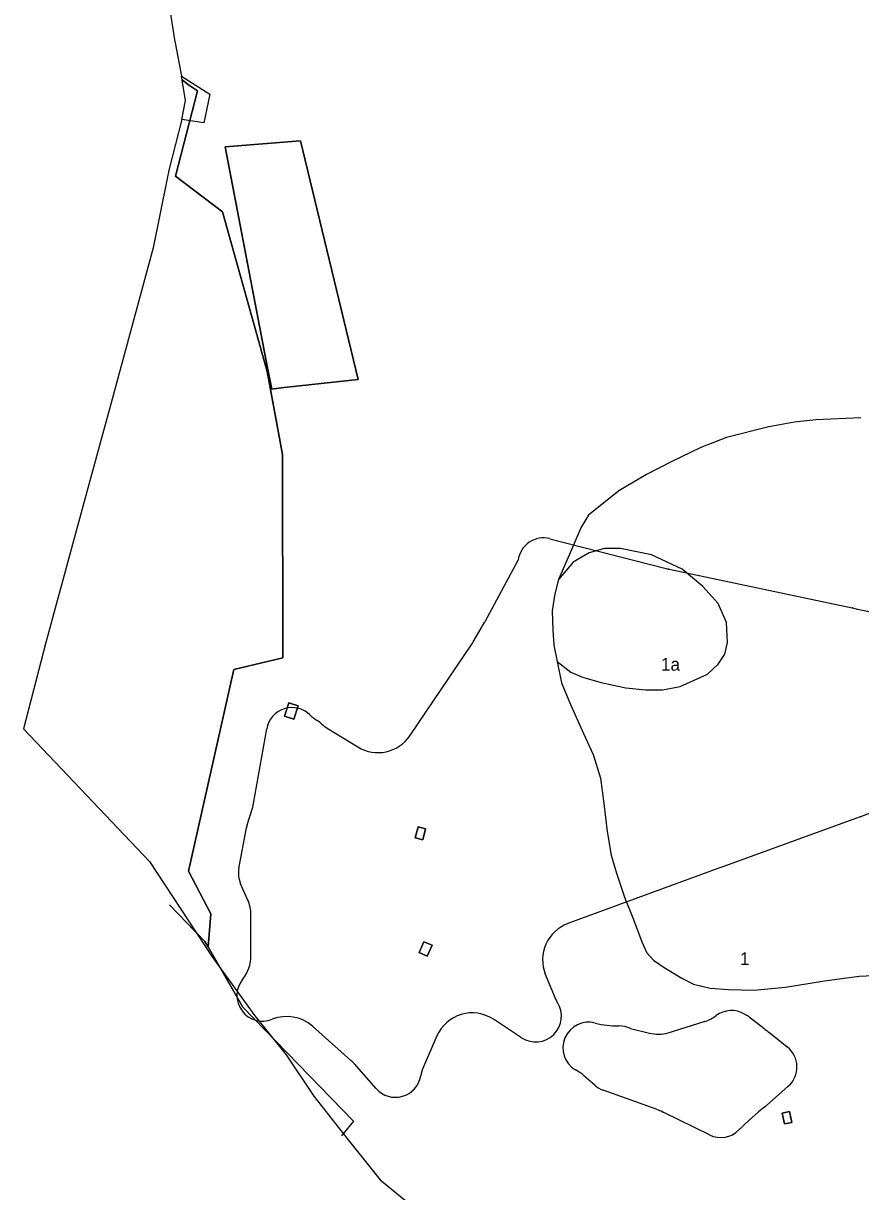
# Model space of a CAD drawing. Extents: x -445049 to -436194, y -1142460 to -1129816.
# Drawn here: x -445049 to -444397, y -1134043 to -1133134 of the extents above; entities that cross this region are included whole.
import ezdxf

# ---------------------------------------------------------------- set-up
doc = ezdxf.new("R2010")
doc.units = 0
for name, color, linetype in [('Vrstva 11', 7, 'Continuous'), ('Vrstva 23', 7, 'Continuous'), ('Vrstva 51', 7, 'Continuous'), ('Vrstva 7', 7, 'Continuous'), ('Vrstva 8', 7, 'Continuous'), ('Vrstva 9', 7, 'Continuous')]:
    doc.layers.add(name, color=color, linetype=linetype)

msp = doc.modelspace()

# ---------------------------------------------------------------- linework, layer by layer
at = {"layer": 'Vrstva 11'}
msp.add_lwpolyline([(-444919.06, -1133836.95), (-444908.06, -1133848.32), (-444905.39, -1133852.69), (-444878.28, -1133899.45), (-444792.06, -1133988.36), (-444801.63, -1133999.84)], dxfattribs=at)
at = {"layer": 'Vrstva 23'}
for p, q in [((-444639.15, -1133534.8), (-444548.63, -1133558.13)), ((-444689.66, -1133599.19), (-444663.98, -1133551.58)), ((-444546.35, -1133558.59), (-444403.74, -1133588.67)), ((-444698.97, -1133615.18), (-444690.15, -1133600.06)), ((-444748.27, -1133688.2), (-444700.03, -1133616.87)), ((-444870.02, -1133740.87), (-444859.79, -1133682.84)), ((-444812.61, -1133682.29), (-444788.88, -1133696.93)), ((-444282.12, -1133707.42), (-444397.22, -1133751.29)), ((-444875.02, -1133757.5), (-444870.97, -1133744.75)), ((-444397.52, -1133751.4), (-444505.41, -1133790.51)), ((-444881.47, -1133791.72), (-444875.63, -1133759.94)), ((-444505.53, -1133790.55), (-444625.29, -1133834.55)), ((-444874.66, -1133815.63), (-444880.07, -1133803.47)), ((-444872.06, -1133859.32), (-444872.06, -1133827.84)), ((-444642.81, -1133873.83), (-444636.02, -1133890.84)), ((-444487.62, -1133904.91), (-444485.19, -1133906.33)), ((-444794.16, -1133940.98), (-444824.22, -1133914.35)), ((-444661.26, -1133923.37), (-444683.23, -1133908.95)), ((-444576.37, -1133916.23), (-444561.62, -1133919.78)), ((-444547.11, -1133919.66), (-444519.18, -1133910.85)), ((-444482.87, -1133907.91), (-444472.63, -1133916.01)), ((-444727.17, -1133921.97), (-444737.71, -1133946.01)), ((-444468.03, -1133919.65), (-444454.39, -1133930.44)), ((-444774.57, -1133962.94), (-444791.51, -1133943.64)), ((-444615.08, -1133950.97), (-444619.34, -1133948.43)), ((-444604.09, -1133960.51), (-444613.05, -1133952.69)), ((-444453.54, -1133961.1), (-444470.43, -1133976.06)), ((-444555.69, -1133979.27), (-444597.67, -1133964.28)), ((-444514.99, -1133999.04), (-444550.55, -1133981.65))]:
    msp.add_line(p, q, dxfattribs=at)
for centre, radius, start, end in [((-444644.14, -1133554.16), 20, 75.54859, 172.58816), ((-444541.75, -1133528.93), 30, 256.73332, 259.94584), ((-444550.48, -1133578.16), 20, 78.0886, 79.94584), ((-444407.87, -1133608.24), 20, 77.17539, 78.0886), ((-443775.03, -1130828.32), 2831.04, 257.17539, 258.46568), ((-444716.06, -1133584.95), 30, 329.73804, 331.65322), ((-444724.88, -1133600.06), 30, 325.93078, 329.73804), ((-444840.09, -1133686.32), 20, 45.52263, 170.00002), ((-444805.06, -1133650.64), 30, 225.52263, 239.14725), ((-444830.7, -1133693.57), 20, 47.41061, 59.14725), ((-444796.86, -1133656.75), 30, 227.41061, 238.32889), ((-444773.12, -1133671.4), 30, 238.32889, 325.93078), ((-444899.56, -1133735.66), 30, 342.37451, 350.00002), ((-444404.34, -1133732.6), 20, 289.92483, 290.86445), ((-444855.96, -1133763.55), 20, 162.37451, 169.58083), ((-444861.8, -1133795.33), 20, 169.58083, 204.00983), ((-444495.18, -1133818.71), 30, 109.92483, 110.17375), ((-444902.06, -1133827.84), 30, 0, 24.00983), ((-444614.94, -1133862.71), 30, 110.17375, 201.74921), ((-444902.06, -1133859.32), 30, 321.43543, 360), ((-444862.97, -1133890.49), 20, 141.43543, 292.14799), ((-444650.28, -1133906.65), 20, 236.71461, 32.59125), ((-444608.16, -1133879.72), 30, 201.74921, 212.59125), ((-444844.12, -1133936.8), 30, 48.46179, 112.14799), ((-444699.7, -1133934.02), 30, 56.71461, 156.31887), ((-444527.28, -1133882.45), 29.52, 286.56502, 306.66618), ((-444497.71, -1133922.17), 20, 59.70458, 126.66618), ((-444495.28, -1133923.59), 20, 51.65172, 59.70458), ((-444609.07, -1133931.26), 20, 74.96204, 239.11851), ((-444586.93, -1133848.85), 65.33, 254.96204, 271.14322), ((-444585.23, -1133934.17), 20, 63.71928, 91.14322), ((-444513.16, -1133929.92), 20, 106.56502, 107.51827), ((-444485.04, -1133931.69), 20, 51.6254, 51.65172), ((-440524.15, -1128929.74), 6360.3, 231.625402, 231.678042), ((-444554.61, -1133890.61), 30, 256.47765, 284.46011), ((-444480.44, -1133935.33), 20, 51.65172, 51.67804), ((-444466.79, -1133946.13), 20, 311.52344, 51.65172), ((-444814.05, -1133963.44), 30, 41.28493, 48.46179), ((-444710.24, -1133958.06), 30, 156.31887, 170.4207), ((-444621.79, -1133960.61), 11.74, 46.39566, 55.18252), ((-444599.89, -1133937.62), 20, 226.39566, 228.87629), ((-444759.54, -1133949.74), 20, 221.28493, 350.4207), ((-444590.94, -1133945.44), 20, 228.87629, 250.34971), ((-444565.86, -1134007.49), 30, 61.17617, 70.18128), ((-444341.71, -1134143.62), 211.25, 127.87599, 135.3404), ((-444483.69, -1133961.09), 20, 307.87599, 311.52344), ((-444541.76, -1133963.68), 20, 241.17617, 243.9304), ((-444506.2, -1133981.08), 20, 243.9304, 315.3404)]:
    msp.add_arc(centre, radius, start, end, dxfattribs=at)
at = {"layer": 'Vrstva 51'}
for points in [[(-444397.1, -1133440.8), (-444432.19, -1133442.27), (-444448.8, -1133444.11), (-444468.62, -1133447.77), (-444501.66, -1133456.09), (-444521.79, -1133463.83), (-444544.75, -1133474.97), (-444564.01, -1133484.84), (-444585.55, -1133497.62), (-444609.08, -1133516.43), (-444614.93, -1133525.77), (-444624.3, -1133547.7), (-444632.41, -1133566.64), (-444635.3, -1133577.74), (-444637.33, -1133590.96), (-444636.91, -1133605.91), (-444636.26, -1133617.79), (-444633.6, -1133630.34), (-444630.23, -1133647.06), (-444623.27, -1133664.04), (-444613.12, -1133686.41), (-444605.62, -1133702.93), (-444599.8, -1133721.37), (-444597.17, -1133741.12), (-444594.69, -1133762.91), (-444591.44, -1133781.16), (-444587.36, -1133795.36), (-444581.03, -1133813.84), (-444574.12, -1133831.34), (-444567.71, -1133848.79), (-444563.72, -1133857.33), (-444558.48, -1133862.86), (-444550.17, -1133868.63), (-444536.38, -1133876.87), (-444527.48, -1133881.66), (-444514.34, -1133884.7), (-444500.01, -1133885.78), (-444480.49, -1133886.22), (-444455.63, -1133883.97), (-444425.42, -1133879.04), (-444398.4, -1133875.42), (-444376.72, -1133874.47)], [(-444633.6, -1133630.34), (-444622.92, -1133638.86), (-444613.94, -1133642.62), (-444599.34, -1133646.81), (-444580.09, -1133650.83), (-444564.78, -1133652.49), (-444551.41, -1133652.47), (-444537.84, -1133649.89), (-444516.53, -1133640.17), (-444508.24, -1133632.56), (-444503.02, -1133624.73), (-444500.79, -1133615.63), (-444501.68, -1133600.13), (-444508.28, -1133585.23), (-444520.15, -1133571.99), (-444536.1, -1133558.44), (-444559.97, -1133547.39), (-444584.29, -1133542.47), (-444596.65, -1133542.57), (-444608.72, -1133545.78), (-444621.1, -1133553.08), (-444632.41, -1133566.64)]]:
    msp.add_lwpolyline(points, dxfattribs=at)
at = {"layer": 'Vrstva 7'}
for points in [[(-444936.13, -1133117.86), (-444931.51, -1133146.3), (-444931.04, -1133148.77), (-444926.06, -1133174.74), (-444904.02, -1133188.79), (-444908.77, -1133210.95), (-444925.81, -1133208.5), (-444935.79, -1133246.77), (-444937.58, -1133255.62), (-444948.21, -1133308.28), (-444981, -1133429.13), (-444999.76, -1133498.43), (-445031.67, -1133615.64), (-445049.3, -1133682.89), (-444951.13, -1133786.04), (-444902.38, -1133860.41), (-444869.15, -1133906.24), (-444844.6, -1133936.67), (-444823, -1133968.9), (-444797.25, -1134001.66), (-444771.32, -1134034.06), (-444712.62, -1134082.03)], [(-444936.13, -1133117.86), (-444931.51, -1133146.3), (-444931.04, -1133148.77), (-444926.06, -1133174.74), (-444904.02, -1133188.79), (-444908.77, -1133210.95), (-444925.81, -1133208.5), (-444935.79, -1133246.77), (-444937.58, -1133255.62), (-444948.21, -1133308.28), (-444981, -1133429.13), (-444999.76, -1133498.43), (-445031.67, -1133615.64), (-445049.3, -1133682.89), (-444951.13, -1133786.04), (-444902.38, -1133860.41), (-444869.15, -1133906.24), (-444844.6, -1133936.67), (-444823, -1133968.9), (-444797.25, -1134001.66), (-444771.32, -1134034.06), (-444712.62, -1134082.03)], [(-444936.13, -1133117.86), (-444931.51, -1133146.3), (-444931.04, -1133148.77), (-444926.06, -1133174.74), (-444904.02, -1133188.79), (-444908.77, -1133210.95), (-444925.81, -1133208.5), (-444935.79, -1133246.77), (-444937.58, -1133255.62), (-444948.21, -1133308.28), (-444981, -1133429.13), (-444999.76, -1133498.43), (-445031.67, -1133615.64), (-445049.3, -1133682.89), (-444951.13, -1133786.04), (-444902.38, -1133860.41), (-444869.15, -1133906.24), (-444844.6, -1133936.67), (-444823, -1133968.9), (-444797.25, -1134001.66), (-444771.32, -1134034.06), (-444712.62, -1134082.03)], [(-444892.23, -1133229.79), (-444833.35, -1133225.06), (-444788.44, -1133410.76), (-444843.72, -1133416.93), (-444848.43, -1133417.46), (-444855.87, -1133418.29), (-444859.33, -1133400.37), (-444892.23, -1133229.79)], [(-444855.87, -1133418.29), (-444859.33, -1133400.37), (-444892.23, -1133229.79), (-444833.35, -1133225.06), (-444788.44, -1133410.76), (-444843.72, -1133416.93), (-444848.43, -1133417.46), (-444855.87, -1133418.29)], [(-444833.35, -1133225.06), (-444788.44, -1133410.76), (-444843.72, -1133416.93), (-444848.43, -1133417.46), (-444855.87, -1133418.29), (-444859.33, -1133400.37), (-444892.23, -1133229.79), (-444833.35, -1133225.06)], [(-444855.87, -1133418.29), (-444859.33, -1133400.37), (-444892.23, -1133229.79), (-444833.35, -1133225.06), (-444788.44, -1133410.76), (-444843.72, -1133416.93), (-444848.43, -1133417.46), (-444855.87, -1133418.29)], [(-444835.28, -1133664.92), (-444838.73, -1133675.28), (-444845.94, -1133672.88), (-444842.49, -1133662.52), (-444835.28, -1133664.92)], [(-444835.28, -1133664.92), (-444838.73, -1133675.28), (-444845.94, -1133672.88), (-444842.49, -1133662.52), (-444835.28, -1133664.92)], [(-444838.73, -1133675.28), (-444845.94, -1133672.88), (-444842.49, -1133662.52), (-444835.28, -1133664.92), (-444838.73, -1133675.28)], [(-444735.99, -1133760.59), (-444738.31, -1133769.28), (-444744.11, -1133767.73), (-444741.79, -1133759.04), (-444735.99, -1133760.59)], [(-444741.79, -1133759.04), (-444735.99, -1133760.59), (-444738.31, -1133769.28), (-444744.11, -1133767.73), (-444741.79, -1133759.04)], [(-444741.79, -1133759.04), (-444735.99, -1133760.59), (-444738.31, -1133769.28), (-444744.11, -1133767.73), (-444741.79, -1133759.04)], [(-444731.01, -1133851.39), (-444734.72, -1133859.73), (-444741.05, -1133856.91), (-444737.35, -1133848.57), (-444731.01, -1133851.39)], [(-444741.05, -1133856.91), (-444737.35, -1133848.57), (-444731.01, -1133851.39), (-444734.72, -1133859.73), (-444741.05, -1133856.91)], [(-444737.35, -1133848.57), (-444731.01, -1133851.39), (-444734.72, -1133859.73), (-444741.05, -1133856.91), (-444737.35, -1133848.57)], [(-444452.52, -1133980.92), (-444450.77, -1133989.24), (-444456.56, -1133990.45), (-444458.3, -1133982.13), (-444452.52, -1133980.92)], [(-444452.52, -1133980.92), (-444450.77, -1133989.24), (-444456.56, -1133990.45), (-444458.3, -1133982.13), (-444452.52, -1133980.92)], [(-444450.77, -1133989.24), (-444456.56, -1133990.45), (-444458.3, -1133982.13), (-444452.52, -1133980.92), (-444450.77, -1133989.24)]]:
    msp.add_lwpolyline(points, dxfattribs=at)
for points in [[(-444926.06, -1133174.74), (-444904.02, -1133188.79), (-444908.77, -1133210.95), (-444925.81, -1133208.5), (-444922.98, -1133193.59)], [(-444892.23, -1133229.79), (-444859.33, -1133400.37), (-444855.87, -1133418.29), (-444848.43, -1133417.46), (-444843.72, -1133416.93), (-444788.44, -1133410.76), (-444833.35, -1133225.06)], [(-444835.28, -1133664.92), (-444842.49, -1133662.52), (-444845.94, -1133672.88), (-444838.73, -1133675.28)], [(-444735.99, -1133760.59), (-444741.79, -1133759.04), (-444744.11, -1133767.73), (-444738.31, -1133769.28)], [(-444731.01, -1133851.39), (-444737.35, -1133848.57), (-444741.05, -1133856.91), (-444734.72, -1133859.73)], [(-444452.52, -1133980.92), (-444458.3, -1133982.13), (-444456.56, -1133990.45), (-444450.77, -1133989.24)]]:
    msp.add_lwpolyline(points, close=True, dxfattribs=at)
at = {"layer": 'Vrstva 8'}
for p, q in [((-444920.58, -1133181.33), (-444925.59, -1133177.64)), ((-444792.06, -1133988.36), (-444801.63, -1133999.84))]:
    msp.add_line(p, q, dxfattribs=at)
msp.add_lwpolyline([(-444792.06, -1133988.36), (-444878.28, -1133899.45), (-444905.39, -1133852.69), (-444903.38, -1133826.78), (-444920.74, -1133793.55), (-444885.45, -1133636.62), (-444847.33, -1133627.57), (-444847.6, -1133469.14), (-444859.47, -1133404.71), (-444894.17, -1133280.32), (-444930.79, -1133252.49), (-444913.72, -1133186.1), (-444920.58, -1133181.33)], dxfattribs=at)
at = {"layer": 'Vrstva 9'}
msp.add_lwpolyline([(-444925.59, -1133177.64), (-444920.58, -1133181.33), (-444913.72, -1133186.1), (-444930.79, -1133252.49), (-444894.17, -1133280.32), (-444859.47, -1133404.71), (-444847.6, -1133469.14), (-444847.33, -1133627.57), (-444885.45, -1133636.62), (-444920.74, -1133793.55), (-444903.38, -1133826.78), (-444905.39, -1133852.69), (-444908.06, -1133848.32), (-444935.47, -1133819.99)], dxfattribs=at)

# ---------------------------------------------------------------- texts
at = {"layer": 'Vrstva 51'}
for s, p in [('1a', (-444552.73, -1133637.6)), ('1', (-444491.2, -1133866.84))]:
    msp.add_text(s, height=10, dxfattribs=at).set_placement(p)

doc.saveas('drawing.dxf')
